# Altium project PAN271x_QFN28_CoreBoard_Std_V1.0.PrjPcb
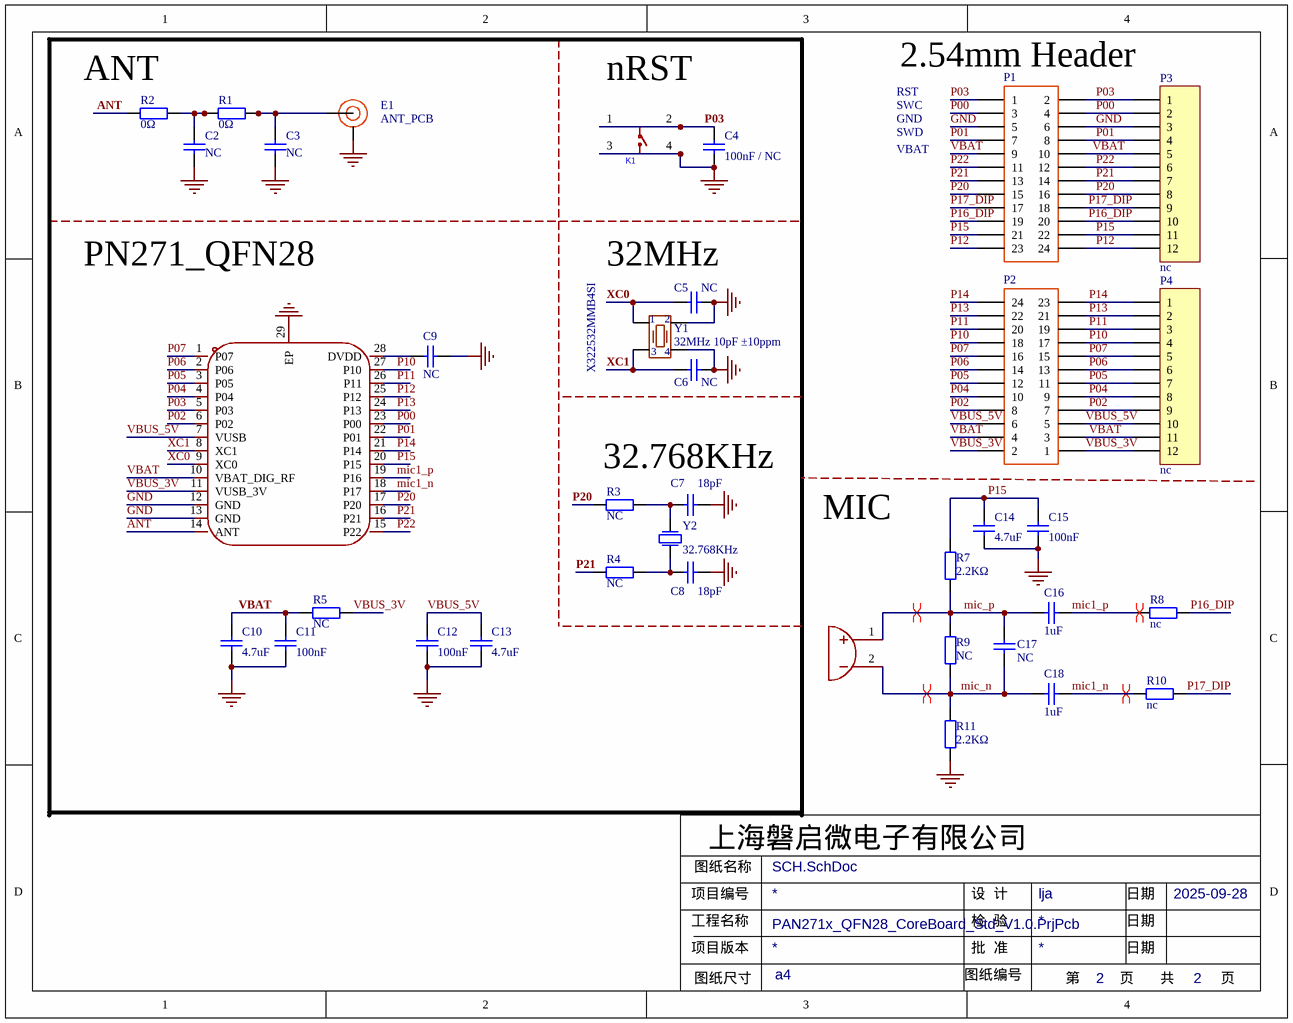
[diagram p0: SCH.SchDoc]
1 sheet, 37 parts. Net scope: global (net labels, ports and power ports of the same name join across sheets).
Board file: PCB.PcbDoc

## Sheet SCH.SchDoc
size A; Date: 2025-9-28; Author: lja; CompanyName: 上海磐启微电子有限公司; DocumentNumber: 2; SheetNumber: 2; SheetTotal: 2; ProjectName1: PN108xMPB

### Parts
C2  NC  [0402_C]
C3  NC  [0402_C]
C4  100nF / NC  [0402_C]
C5  NC  [0402_C]
C6  NC  [0402_C]
C7  18pF  [0402_C]
C8  18pF  [0402_C]
C9  NC  [0402_C]
C10  4.7uF  [0402_C]
C11  100nF  [0402_C]
C12  100nF  [0402_C]
C13  4.7uF  [0402_C]
C14  4.7uF  [0402_C]
C15  100nF  [0402_C]
C16  1uF  [0402_C]
C17  NC  [0402_C]
C18  1uF  [0402_C]
E1  ANT_PCB  [2.4G_PF_SUB1.5mm_ADD1]
K1  K2-1808GN-A4SW-04  [KEY-SMD_4P-L4.2-W3.2-P2.20-LS5.1-TL]  (value not drawn)
MIC1  GMI4015P-2C-60db  [MIC-TH_BD4.0-P1.40-D0.4-L-FD]  (value not drawn)
P1  Header 2x12  [Header 2X12]  (value not drawn)
P2  Header 2x12  [Header 2X12]  (value not drawn)
P3  nc  [HDR1X12]
P4  nc  [HDR1X12]
R1  0Ω  [0402_R]
R2  0Ω  [0402_R]
R3  NC  [0402_R]
R4  NC  [0402_R]
R5  NC  [0402_R]
R7  2.2KΩ  [0402_R]
R8  nc  [0402_R]
R9  NC  [0402_R]
R10  nc  [0402_R]
R11  2.2KΩ  [0402_R]
U1  pn271_qfn28  [QFN28_L4.0_W4.0_P0.40_BL_EP]  (value not drawn)
Y1  32MHz 10pF ±10ppm  [SMD-3225_4P_S]
Y2  32.768KHz  [SMD-3215_2P FC - 135]

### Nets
GND: C2.2 C3.2 C4.1 C5.2 C6.2 C7.2 C8.2 C9.1 C10.1 C11.1 C12.1 C13.1 C14.1 C15.1 E1.2(GND) K1.3 K1.4 P1.5 P1.6 P3.3 R11.1 U1.12(GND) U1.13(GND) U1.29(EP) Y1.2(GND) Y1.4(GND)
ANT: R2.1 U1.14(ANT)
mic1_n: C18.1 R10.2 U1.18(P17)
mic1_p: C16.1 R8.2 U1.19(P16)
mic_n: C17.2 C18.2 MIC1.2 R9.1 R11.2
mic_p: C16.2 C17.1 MIC1.1 R7.1 R9.2
P00: P1.3 P1.4 P3.2 U1.23(P00)
P01: P1.7 P1.8 P3.4 U1.22(P01)
P02: P2.7 P2.8 P4.9 U1.6(P02)
P03: C4.2 K1.1 K1.2 P1.1 P1.2 P3.1 U1.5(P03)
P04: P2.9 P2.10 P4.8 U1.4(P04)
P05: P2.11 P2.12 P4.7 U1.3(P05)
P06: P2.13 P2.14 P4.6 U1.2(P06)
P07: P2.15 P2.16 P4.5 U1.1(P07)
P10: P2.17 P2.18 P4.4 U1.27(P10)
P11: P2.19 P2.20 P4.3 U1.26(P11)
P12: P1.23 P1.24 P3.12 U1.25(P12)
P13: P2.21 P2.22 P4.2 U1.24(P13)
P14: P2.23 P2.24 P4.1 U1.21(P14)
P15: C14.2 C15.2 P1.21 P1.22 P3.11 R7.2 U1.20(P15)
P16_DIP: P1.19 P1.20 P3.10 R8.1
P17_DIP: P1.17 P1.18 P3.9 R10.1
P20: P1.15 P1.16 P3.8 R3.1 U1.17(P20)
P21: P1.13 P1.14 P3.7 R4.1 U1.16(P21)
P22: P1.11 P1.12 P3.6 U1.15(P22)
VBAT: C10.2 C11.2 P1.9 P1.10 P2.3 P2.4 P3.5 P4.11 R5.1 U1.10(VBAT_DIG_RF)
VBUS_3V: P2.1 P2.2 P4.12 R5.2 U1.11(VUSB_3V)
VBUS_5V: C12.2 C13.2 P2.5 P2.6 P4.10 U1.7(VUSB)
XC0: C5.1 U1.9(XC0) Y1.1(D1)
XC1: C6.1 U1.8(XC1) Y1.3(D2)
NetC2_1: C2.1 R1.1 R2.2
NetC3_1: C3.1 E1.1(ANT) R1.2
NetC7_1: C7.1 R3.2 Y2.1
NetC8_1: C8.1 R4.2 Y2.2
NetC9_2: C9.2 U1.28(DVDD)

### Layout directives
differential pair: mic1_n, mic1_p, mic_n, mic_p

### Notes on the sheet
- (near R2) ANT
- (near K1) nRST
- RST
- 2.54mm Header
- SWC
- GND
- SWD
- VBAT
- PN271_QFN28
- (near C5) 32MHz
- 32.768KHz
- MIC
- 项目编号
- 图纸名称
- 设  计
- lja
- 日期
- 2025-09-28
- 项目版本
- 工程名称
- 检  验
- 批  准
- 图纸尺寸
- a4
- 图纸编号
- 第
- 页
- 共

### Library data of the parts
C2 C3 = 0402 1nF (102) 10% 50V: 贴片电容
C4 C9 C13 = 0402 100nF (104) 10% 16V: 贴片电容
C5-C8 = 0402 20pF (200) 5% 50V: 贴片电容
C10-C12 C14-C18 = 0402 4.7uF (475) 20% 10V: 贴片电容
E1 = ANT_PCB: 2.4GHz PCB ANTENNA
K1 = K2-1808GN-A4SW-04: Manufacturer: 韩国韩荣; Add into BOM: yes; Circuit: 单刀单掷; Actuator Style: 椭圆形按钮; Operating Force: 250gf; Switch Length: 4.2mm; Switch Width: 3.25mm; Switch Height: 2.5mm; Contact Current: 50mA; Voltage Rating (DC): 12V; Insulation Resistance: 100MΩ; Mechanical Life: 10万次
MIC1 = GMI4015P-2C-60db: Manufacturer: INGHAi(赢海); Add into BOM: yes
P1 P2 = Header 2x12: Header 2x11,2.54mm
P3 P4 = Header 12: Header, 12-Pin
R1-R5 R8-R11 = 0402 0Ω (0R0) 1%: 贴片电阻
R7 = 0402 2.2KΩ (2201) 1%: 贴片电阻
Y1 = Crystal 4pin: C113671
Y2 = DT26N 32.768KHz: C620155, X321532768KGD2SI,12.5pF; 编码: 38501164A; 名称: 柱形晶振; 价格: 0.31; 品牌: 晶峰晶体; 税点: 17%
